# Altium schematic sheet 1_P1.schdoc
size 309 x 223 mm; Symbol: Sheet-Symbol_A4; Device: Sheet-Symbol_A4; @Page Name: P1; @Create Date: 2023-09-13; @Page Count: 1; @Page No: 1; @Project Name: 基于STM32的红外热成像; @Schematic Name: Schematic2; @Update Date: 2023-09-15; Company: 嘉立创EDA; Page Size: A4; Version: V1.0
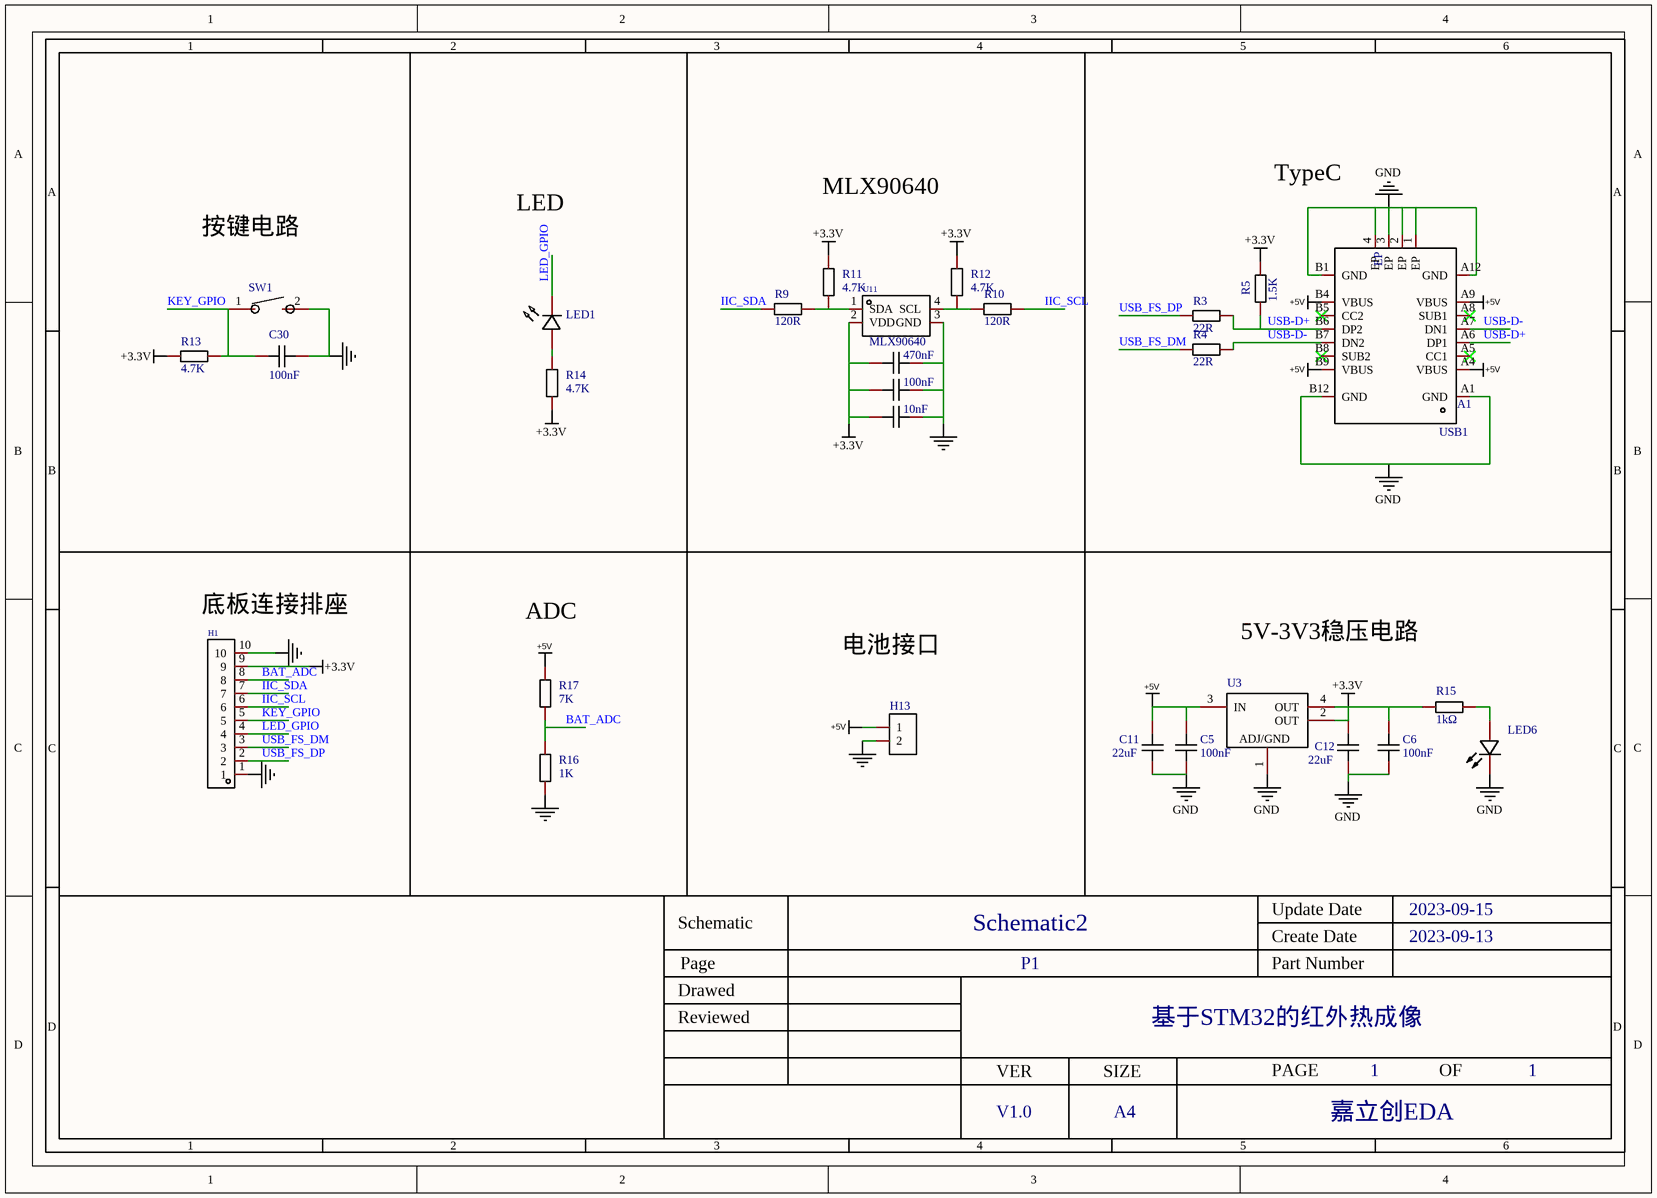
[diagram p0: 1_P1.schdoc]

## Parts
C5  value 100nF  [C0603]  (hidden comment: HMK107B7104KA-T)
C6  value 100nF  [C0603]  (hidden comment: HMK107B7104KA-T)
C11  value 22uF  [C0603]  (hidden comment: GRM186R60J226ME15D)
C12  value 22uF  [C0603]  (hidden comment: GRM186R60J226ME15D)
C27  470nF  [C0603]
C28  100nF  [C0603]
C29  10nF  [C0603]
C30  100nF  [C0603]
H1  KH-1.27PH180-1X10P-L7.2  [HDR-TH_10P-P1.27-V-M]  (value not drawn)
H13  HDR-F_2.54_1x2P  [HDR-TH_2P-P2.54-V-F]  (value not drawn)
LED1  LED_0603-R  [LED_0603]  (value not drawn)
LED6  SZYY0603B  [LED0603-R-RD_BLUE]  (value not drawn)
R3  22R  [R0603]
R4  22R  [R0603]
R5  1.5K  [R0603]
R9  120R  [R0603]
R10  120R  [R0603]
R11  4.7K  [R0603]
R12  4.7K  [R0603]
R13  4.7K  [R0603]
R14  4.7K  [R0603]
R15  value 1kΩ  [R0603]  (hidden comment: ERJ3GEYJ102V)
R16  1K  [R0603]
R17  7K  [R0603]
SW1  TSA363G25-250B  [SW-SMD_L6.1-W3.6-LS8.0]  (value not drawn)
U3  AMS1117-3.3_1  [SOT-223-3_L6.4-W3.5-P2.30-LS7.0-BR]  (value not drawn)
U11  MLX90640  [TO-39-4_MELEXIS_MLX90640]
USB1  NAME: EP  NUMBER: A1  [usb-c-smd_kh-type-c-16p]  (hidden comment: kh-type-c-16p)

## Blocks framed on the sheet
按键电路: C30 R13 SW1
LED: LED1 R14
MLX90640: C27-C29 R9-R12 U11
TypeC: R3-R5 USB1
底板连接排座: H1
ADC: R16 R17
电池接口: H13
5V-3V3稳压电路: C5 C6 C11 C12 LED6 R15 U3

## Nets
+3.3V: C6.2 C12.1 C27.2 C28.2 C29.2 H1.9 R5.1 R11.1 R12.1 R13.1 R14.1 R15.1 U3.2(OUT) U3.4(OUT) U11.2(VDD)
+5V: C5.2 C11.1 H13.1 R17.2 U3.3(IN) USB1.A4(VBUS) USB1.A9(VBUS) USB1.B4(VBUS) USB1.B9(VBUS)
GND: C5.1 C6.1 C11.2 C12.2 LED6.2(-) U3.1(ADJ/GND) USB1.1(EP) USB1.2(EP) USB1.3(EP) USB1.4(EP) USB1.A1(GND) USB1.A12(GND) USB1.B1(GND) USB1.B12(GND)
NetC27_1: C27.1 C28.1 C29.1 C30.2 H1.1 H1.10 H13.2 R16.1 SW1.2 U11.3(GND)
BAT_ADC: H1.8 R16.2 R17.1
IIC_SCL: H1.6 R10.1
IIC_SDA: H1.7 R9.2
KEY_GPIO: C30.1 H1.5 R13.2 SW1.1
LED_GPIO: H1.4 LED1.1(C)
USB-D+: R3.1 R5.2 USB1.A6(DP1) USB1.B6(DP2)
USB-D-: R4.1 USB1.A7(DN1) USB1.B7(DN2)
USB_FS_DM: H1.3 R4.2
USB_FS_DP: H1.2 R3.2
NetLED1_2: LED1.2(A) R14.2
NetLED6_1: LED6.1(+) R15.2
NetR9_1: R9.1 R11.2 U11.1(SDA)
NetR10_2: R10.2 R12.2 U11.4(SCL)

Not connected (* = marked no-connect by the designer): USB1 A5(CC1)* A8(SUB1)* B5(CC2)* B8(SUB2)*

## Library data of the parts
C5 C6 = HMK107B7104KA-T: 容值:100nF;精度:±10%;额定电压:100V;温度系数:X7R;; Manufacturer: TAIYO YUDEN(太诱); Add into BOM: yes; Tolerance: ±10%; Voltage Rated: 100V; Temperature Coefficient: X7R
C11 C12 = GRM186R60J226ME15D: 容值:22uF;精度:±20%;额定电压:6.3V;温度系数:X5R;; Manufacturer: muRata(村田); Add into BOM: yes; Tolerance: ±20%; Voltage Rated: 6.3V; Temperature Coefficient: X5R
C27-C30 = CAP_0603: Symbol: CapAcitance; Convert to PCB: yes
H1 = KH-1.27PH180-1X10P-L7.2: 排数:单排;总PIN位数:10P;间距:1.27mm;插针结构:1x10P;行距:-;安装类型:直插;圆针/方针:方针;额定电流:1A;额定电压:-;配合针长度:3.9mm;塑高:1mm;端接针长度:2.3mm;工作温度范围:-40℃~+105℃;颜色:-;; Manufacturer: kinghelm(金航标); Add into BOM: yes; Pitch: 1.27mm; Pin Structure: 1x10P; Circluar Pins/Square Pins: 方针; Current Rating (Max): 1A
H13 = HDR-F_2.54_1x2P: Symbol: Header-Female-2.54_1x2; Convert to PCB: yes
LED1 = LED_0603-R: Symbol: LED_R; Convert to PCB: yes
LED6 = SZYY0603B: 发光颜色:蓝灯;二极管配置:-;透镜颜色:无色透明;主波长:460nm~475nm;峰值波长:469nm;色温:-;光通量(25时):-;测试电流:5mA;正向电压(VF):3.1V;发光强度:175mcd;功率:100mW;发光角度:120°;安装方式:-;工作温度:-40~+85;; Manufacturer: yongyu(永裕光电); Add into BOM: yes; Emitted Color: 蓝灯; Lens Color: 无色透明; Peak Wavelength: 469nm; Forward Current: 5mA; Forward Voltage (VF): 3.1V; Luminous Intensity: 175mcd; Power Dissipation: 100mW; Viewing Angle: 120°
R3-R5 R9-R14 R16 R17 = Res_0603: Symbol: 电阻; Convert to PCB: yes
R15 = ERJ3GEYJ102V: 阻值:1kΩ;精度:±5%;功率:1/10W;温度系数:±200ppm/;最大工作电压:150V;工作温度范围:-55~+155;; Manufacturer: PANASONIC(松下); Add into BOM: yes; Tolerance: ±5%; Power(Watts): 1/10W; Overload Voltage (Max): 150V
SW1 = TSA363G25-250B: 触点电流:50mA;额定电压(DC):12V;绝缘电阻:100MΩ;电路结构:单刀单掷;安装方式:立贴;带灯:无;作用力:250gf@±50gf;机械寿命:5万次;带支架:否;; Manufacturer: BRIGHT(博瑞泰); Add into BOM: yes; Contact Current: 50mA; Voltage Rating (DC): 12V; Insulation Resistance: 100MΩ; Circuit: 单刀单掷; Actuator Style: 矩形按钮; Actuator/Cap Color: 白色; With Lamp: 无; Mechanical Life: 5万次; Pin Style: 鸥翼型; Switch Length: 6.05mm; Switch Width: 3.6mm; Switch Height: 2.5mm; Strike Gundam: 否
U3 = AMS1117-3.3_1: Manufacturer: 国芯佳品; Symbol: AMS1117-3.3_C2992570; Add into BOM: yes
U11 = MLX90640ESF-BAB-000-TU: 光学格式(inch):-;有源像素阵列:32Hx24V;像素大小:-;传感器类型:-;; Manufacturer: Melexis(比利时迈来芯); Add into BOM: yes
USB1 = kh-type-c-16p: Type-C母座 16PIN 立式四角贴板无压片; Manufacturer: kinghelm(金航标); Add into BOM: yes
